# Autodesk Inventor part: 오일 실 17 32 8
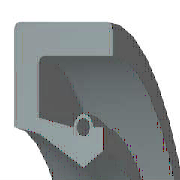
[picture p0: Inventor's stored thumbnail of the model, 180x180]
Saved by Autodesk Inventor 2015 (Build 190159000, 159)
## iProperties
IsCustomPart: 1
Created: 2012-02
Part Number: 오일 실 17 32 8
Material: 고무
Description: 오일-실
Document SubType Name: Modeling
Standard: KS B 2804
Designer: test
Standards Organization: KS
Language: ko-KR
Size Designation: S - 17 32 8
Categories: <MemberInstance><Categories><Category DisplayName="샤프트 부품" InternalName="7f7aeb1f-a693-4053-b835-cee3144e0d98" Mnemonic="SHFT"><Category DisplayName="실링" Intern
Density: 0.93 g/cm^3
Appearance: 고무 - 검은색 - 버전 1.1
Mass: 1.89534 g
Surface Area: 30.829 cm^2
Volume: 2.038 cm^3
Author: test
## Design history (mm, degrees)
revolve "본체" stored, may be unused: angle "d17" = 90 deg
revolve "스프링1" stored, may be unused: angle "d18" = 90 deg
body "Solid1"
sketch "스케치1"
  geometry: L1 (0, 16)-(8, 16); L2 (8, 16)-(8, 14.75); L3 (8, 14.75)-(1.75, 14.75); L4 (0, 16)-(0, 10.6); L5 (0, 10.6)-(1.75, 10.25); L6 (1.75, 10.25)-(4.9, 8.5); L7 (4.9, 8.5)-(0, 8.5); L8 (6.3, 9.375)-(6.3, 10.6); L9 (0, 0)-(9.586, 0) reference; L10 (4.9, 8.5)-(6.3, 9.375); L11 (0, 18)-(0, -3) reference; L12 (-1.917, 0)-(11.503, 0) reference; L13 (4.2, 10.6)-(1.75, 11.09); L14 (1.75, 11.09)-(1.75, 14.75); L15 (6.3, 10.6)-(5.6, 10.6); C1 r 0.455 at (4.9, 10.6); A1 r 0.7 centre (4.9, 10.6) between (5.6, 10.6) and (4.2, 10.6)
  constraints: 26 end point, 5 horizontal alignment, 4 perpendicular, 2 centre point, 2 collinear, 2 horizontal, 2 parallel, 2 point on circle, 2 point on line, 2 vertical alignment, 1 coincident
  dimensions: "d0" = 32 diameter of L1 L9 (= SD2); "d1" = 18.75 diameter of L8.start L9 (= ABDM); "d2" = 1.25 distance of L1.end L2.end (computed from SD); "d3" = 0.91 diameter of C1 (= SPDI); "d4" = 1.4 diameter of A1 (= SPDA); "d5" = 17 diameter of L6.end L9 (= NND); "d6" = 20.5 diameter of L5.end L9 (= TKDM); "d7" = 21.2 diameter of L4.end L9 (= HLDM); "d8" = 4.9 distance from line of C1.centre L4 (= SPDST); "d9" = 6.3 distance between parallel lines of L8 L4 (= SDI); "d10" = 8 distance between parallel lines of L2 L4 (= SWDT); "d12" = 1.75 distance between parallel lines of L14 L4 (= SD)
fillet "모깎기1" dims "d11" = 0.3 (= RR)
other parameters: "SD2" = 32 [user parameter; used in 1 equation term], "SWDT" = 8 [user parameter; used in 1 equation term], "RR" = 0.3 [user parameter; used in 1 equation term], "SD" = 1.75 [user parameter; used in 2 equation terms], "NND" = 17 [user parameter; used in 1 equation term], "SPDA" = 1.4 [user parameter; used in 1 equation term], "SPDI" = 0.91 [user parameter; used in 1 equation term], "TKDM" = 20.5 [user parameter; used in 1 equation term], "HLDM" = 21.2 [user parameter; used in 1 equation term], "ABDM" = 18.75 [user parameter; used in 1 equation term], "SDI" = 6.3 [user parameter; used in 1 equation term], "SPDST" = 4.9 [user parameter; used in 1 equation term], "d13" = 0, "d14" = 0, "d15" = 0, "LAB" = 0.35 [user parameter]
